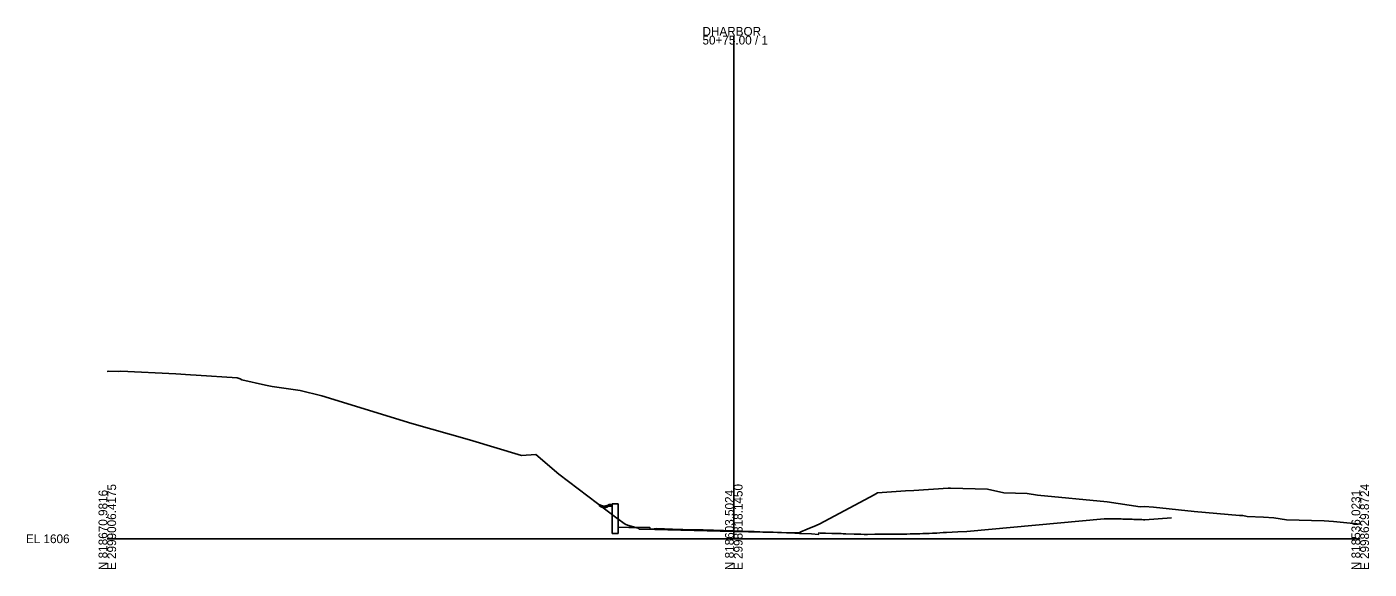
# Model space of a CAD drawing. Extents: x -26 to 1067, y -71 to 1837.
# Drawn here: x 638.3 to 1066.8, y -71.4 to 101.7 of the extents above; entities that cross this region are included whole.
import ezdxf

# ---------------------------------------------------------------- set-up
doc = ezdxf.new("R2010")
doc.units = 0
for name, color, linetype in [('DESIGN - SHEET - Light Grid', 7, 'Continuous'), ('DESIGN - TYPICAL - Finished Grade and Subgrade', 7, 'Continuous'), ('SURVEY - GROUND - Top of Ground', 7, 'Continuous')]:
    doc.layers.add(name, color=color, linetype=linetype)

msp = doc.modelspace()

# ---------------------------------------------------------------- linework, layer by layer
at = {"layer": 'DESIGN - SHEET - Light Grid'}
for p, q in [((863.99, -61.74), (863.99, 98.83)), ((663.99, -61.74), (863.99, -61.74)), ((863.99, -61.74), (1063.99, -61.74))]:
    msp.add_line(p, q, dxfattribs=at)
at = {"layer": 'DESIGN - TYPICAL - Finished Grade and Subgrade'}
for p, q in [((821.13, -51.31), (821.13, -50.81)), ((821.23, -50.87), (821.13, -50.81)), ((821.23, -51.37), (821.13, -51.31)), ((821.33, -50.93), (821.23, -50.87)), ((821.33, -51.43), (821.23, -51.37)), ((821.43, -50.98), (821.33, -50.93)), ((821.53, -51.03), (821.43, -50.98)), ((821.63, -51.08), (821.53, -51.03)), ((821.73, -51.12), (821.63, -51.08)), ((821.83, -51.16), (821.73, -51.12)), ((821.93, -51.19), (821.83, -51.16)), ((822.03, -51.22), (821.93, -51.19)), ((822.13, -51.25), (822.03, -51.22)), ((822.23, -51.27), (822.13, -51.25)), ((822.33, -51.28), (822.23, -51.27)), ((822.43, -51.29), (822.33, -51.28)), ((822.53, -51.3), (822.43, -51.29)), ((822.63, -51.3), (822.53, -51.3)), ((822.73, -51.3), (822.63, -51.3)), ((822.83, -51.29), (822.73, -51.3)), ((822.93, -51.28), (822.83, -51.29)), ((823.03, -51.27), (822.93, -51.28)), ((823.13, -51.25), (823.03, -51.27)), ((823.23, -51.22), (823.13, -51.25)), ((823.33, -51.19), (823.23, -51.22)), ((823.43, -51.16), (823.33, -51.19)), ((823.53, -51.12), (823.43, -51.16)), ((823.63, -51.08), (823.53, -51.12)), ((823.73, -51.03), (823.63, -51.08)), ((823.83, -50.98), (823.73, -51.03)), ((823.93, -50.93), (823.83, -50.98)), ((824.03, -50.87), (823.93, -50.93)), ((824.03, -51.37), (823.93, -51.43)), ((824.13, -50.81), (824.03, -50.87)), ((824.13, -51.31), (824.03, -51.37)), ((825.13, -50.81), (824.13, -50.81)), ((824.13, -51.31), (824.13, -50.81)), ((825.13, -51.31), (824.13, -51.31)), ((825.13, -60.05), (825.13, -50.54)), ((825.13, -50.54), (827.13, -50.54)), ((827.13, -60.05), (827.13, -50.54)), ((821.43, -51.48), (821.33, -51.43)), ((821.53, -51.53), (821.43, -51.48)), ((821.63, -51.58), (821.53, -51.53)), ((821.73, -51.62), (821.63, -51.58)), ((821.83, -51.66), (821.73, -51.62)), ((821.93, -51.69), (821.83, -51.66)), ((822.03, -51.72), (821.93, -51.69)), ((822.13, -51.75), (822.03, -51.72)), ((822.23, -51.77), (822.13, -51.75)), ((822.33, -51.78), (822.23, -51.77)), ((822.43, -51.79), (822.33, -51.78)), ((822.53, -51.8), (822.43, -51.79)), ((822.63, -51.8), (822.53, -51.8)), ((822.73, -51.8), (822.63, -51.8)), ((822.83, -51.79), (822.73, -51.8)), ((822.93, -51.78), (822.83, -51.79)), ((823.03, -51.77), (822.93, -51.78)), ((823.13, -51.75), (823.03, -51.77)), ((823.23, -51.72), (823.13, -51.75)), ((823.33, -51.69), (823.23, -51.72)), ((823.43, -51.66), (823.33, -51.69)), ((823.53, -51.62), (823.43, -51.66)), ((823.63, -51.58), (823.53, -51.62)), ((823.73, -51.53), (823.63, -51.58)), ((823.83, -51.48), (823.73, -51.53)), ((823.93, -51.43), (823.83, -51.48)), ((825.13, -60.05), (827.13, -60.05))]:
    msp.add_line(p, q, dxfattribs=at)
msp.add_lwpolyline([(827.13, -58.05), (830.51, -58.09), (832.58, -58.11), (836.8, -58.16), (837.22, -58.16), (837.31, -58.66), (838.59, -58.55), (839.34, -58.49), (844.4, -58.64), (847.69, -58.74), (854.21, -58.94), (863.99, -59.22), (863.99, -59.22), (869.07, -59.4), (870.47, -59.46), (874.17, -59.59), (876.56, -59.68), (879.26, -59.79), (880.8, -59.84), (881.88, -59.88), (885.02, -60.01), (885.53, -60.03), (888.78, -60.17), (891.02, -60.38), (891.12, -59.89), (891.59, -59.9), (893.31, -59.95), (895.31, -60.01), (896.64, -60.05), (897.6, -60.08), (898.32, -60.1), (898.9, -60.12), (899.36, -60.13), (899.75, -60.14), (902.47, -60.22), (903.54, -60.26), (904.54, -60.29), (905.63, -60.33), (906.66, -60.37), (909.01, -60.27), (910.04, -60.27), (911.06, -60.28), (912.08, -60.28), (913.11, -60.28), (914.13, -60.28), (915.15, -60.28), (916.18, -60.27), (917.2, -60.26), (918.22, -60.25), (919.25, -60.23), (920.27, -60.21), (921.29, -60.19), (922.32, -60.16), (923.34, -60.13), (924.36, -60.1), (925.39, -60.06), (926.41, -60.02), (927.43, -59.98), (928.45, -59.92), (928.8, -59.92), (929.82, -59.86), (930.85, -59.79), (931.87, -59.72), (935.54, -59.48), (938.42, -59.42), (982.19, -55.37), (982.64, -55.39), (983.19, -55.37), (983.64, -55.39), (984.19, -55.37), (984.65, -55.39), (985.2, -55.37), (985.65, -55.39), (986.2, -55.37), (986.65, -55.4), (987.2, -55.39), (987.66, -55.41), (988.2, -55.43), (988.66, -55.45), (989.21, -55.46), (989.66, -55.48), (990.21, -55.5), (990.75, -55.51), (991.21, -55.53), (991.75, -55.55), (992.21, -55.57), (992.76, -55.58), (993.21, -55.6), (993.76, -55.62), (994.22, -55.64), (994.76, -55.65), (995.22, -55.68), (1003.77, -55.04)], dxfattribs=at)
at = {"layer": 'SURVEY - GROUND - Top of Ground'}
msp.add_lwpolyline([(663.99, -8.3), (664.52, -8.29), (667.45, -8.37), (668.32, -8.22), (685.81, -9.12), (690.54, -9.39), (692.38, -9.49), (705.4, -10.34), (706.4, -10.66), (706.95, -11.03), (714.51, -12.69), (716.64, -13.11), (725.59, -14.42), (732.48, -16.16), (761.16, -24.95), (779.58, -30.14), (796.17, -35.11), (800.83, -34.85), (808.1, -41.08), (826.63, -55.16), (829.3, -57.06), (830.05, -57.44), (833.46, -58.35), (833.83, -58.68), (838.76, -58.8), (859.65, -59.33), (863.99, -59.42), (877.9, -59.71), (884.91, -59.86), (885.44, -59.49), (887.45, -58.66), (890.34, -57.55), (891.48, -56.99), (908.78, -47.69), (909.86, -47.04), (918.85, -46.39), (921.42, -46.32), (932.43, -45.55), (932.82, -45.55), (933.2, -45.57), (944.98, -45.87), (950.17, -47.04), (957.68, -47.32), (960.9, -47.8), (983.22, -49.97), (993.7, -51.52), (995.16, -51.43), (997.95, -51.68), (1011, -52.99), (1025.47, -54.34), (1026.52, -54.34), (1027.84, -54.58), (1033.07, -54.81), (1036.37, -55.01), (1040.4, -55.69), (1052.46, -56.05), (1053.98, -56.11), (1055.41, -56.25), (1063.99, -57.07)], dxfattribs=at)

# ---------------------------------------------------------------- texts
at = {"layer": 'DESIGN - SHEET - Light Grid'}
for s, p in [('50+75.00 / 1', (853.99, 96.03)), ('DHARBOR', (853.99, 98.83)), ('EL 1606', (637.99, -63.14))]:
    msp.add_text(s, height=2.8, dxfattribs=at).set_placement(p)
for s, p in [('N 818670.9816', (663.99, -71.74)), ('E 2999006.4175', (666.79, -71.74)), ('N 818603.5024', (863.99, -71.74)), ('E 2998818.1450', (866.79, -71.74)), ('N 818536.0231', (1063.99, -71.74)), ('E 2998629.8724', (1066.79, -71.74))]:
    msp.add_text(s, height=2.8, rotation=90, dxfattribs=at).set_placement(p)

doc.saveas('drawing.dxf')
